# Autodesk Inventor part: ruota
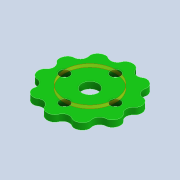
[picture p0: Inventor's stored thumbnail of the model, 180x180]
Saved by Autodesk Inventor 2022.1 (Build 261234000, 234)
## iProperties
Created: 2022-04
Part Number: ruota
Material: Generico
Document SubType Name: Modeling
Designer: i911900
Density: 1 g/cm^3
Appearance: Verde scuro
Mass: 7.50551 g
Surface Area: 49.0359 cm^2
Volume: 7.50551 cm^3
Author: i911900
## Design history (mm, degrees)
sketch "Schizzo1"
  geometry: 2 further points
  constraints: 2 other
extrude "Estrusione1" new body sketch "Schizzo1" distance "d2" = 4; taper "d3" = 0 deg
sketch "Schizzo2"
  geometry: C1 r 5 at (0, 0); 1 further point
  constraints: 1 centre point, 1 coincident
  dimensions: "d4" = 10 diameter of C1
extrude "Estrusione2" cut sketch "Schizzo2" distance "d5" = 8; taper "d6" = 0 deg
sketch "Schizzo3" dims "d7" = 31
  geometry: L1 (0, 0)-(20.321, 0); C1 r 3 at (15.5, 0); 1 further point
  constraints: 2 end point, 1 centre point, 1 coincident, 1 horizontal, 1 horizontal alignment, 1 point on line, 2 other
  dimensions: "d8" = 6 diameter of C1
extrude "Estrusione3" cut sketch "Schizzo3" extent not by distance; stored distance "d9" = 0; taper "d10" = 0 deg
pattern_circular "Serie circolare1" dims angle "d12" = 360 deg
sketch "Schizzo4"
  geometry: C1 r 15.5 at (0, 0); 1 further point
  constraints: 1 centre point, 1 coincident
  dimensions: "d14" = 31 diameter of C1
feature "SupEstrusione1" sketch "Schizzo4" dims "d15" = 2, "d16" = 0
node "Solido1"
node "Curva 2D da equazione1" dims "d0" = 0, "d1" = 3600
node "Superf1"
